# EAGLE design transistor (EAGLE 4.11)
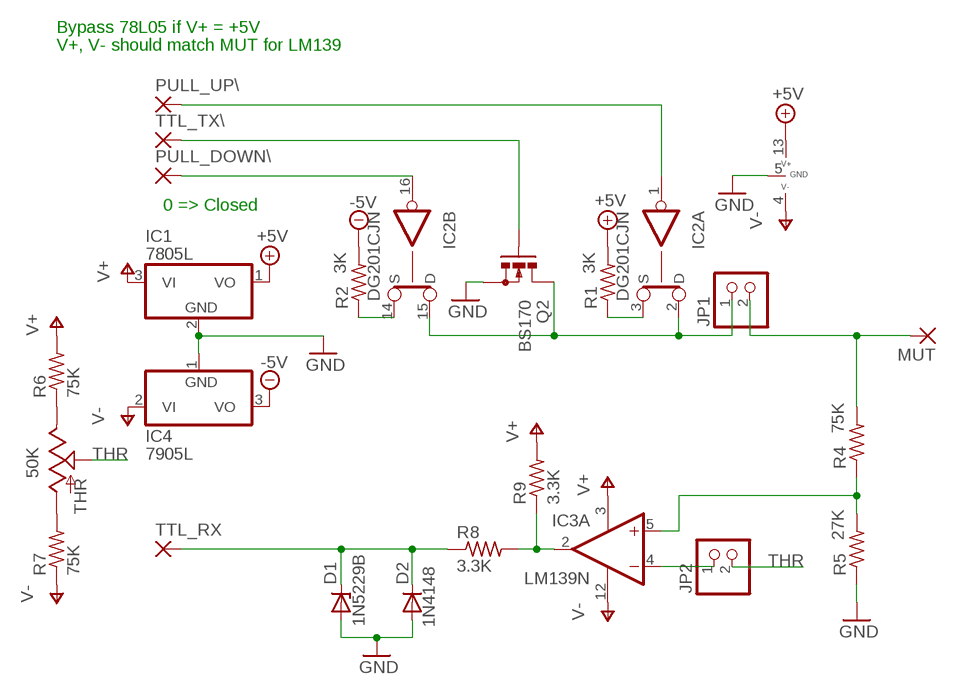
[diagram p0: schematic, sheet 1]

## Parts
D1  1N5229B  ZENER-DIODEDO35Z10  [DO35Z10]
D2  1N4148  [DO35-10]
IC1  7805L  [TO92]
IC2  DG201CJN  [DIL16]
IC3  LM139N  LM339N  [DIL14]
IC4  7905L  [TO92]
JP1  PINHD-1X2  [1X02]
JP2  PINHD-1X2  [1X02]
MUT  1,6/0,9  [1,6/0,9]
PULL_DOWN\  1,6/0,9  [1,6/0,9]
PULL_UP\  1,6/0,9  [1,6/0,9]
Q2  BS170  [SOT54E]
R1  3K  R-US_0207/10  [0207/10]
R2  3K  R-US_0207/10  [0207/10]
R4  75K  R-US_0207/10  [0207/10]
R5  27K  R-US_0207/10  [0207/10]
R6  75K  R-US_0207/10  [0207/10]
R7  75K  R-US_0207/10  [0207/10]
R8  3.3K  R-US_0207/10  [0207/10]
R9  3.3K  R-US_0207/10  [0207/10]
THR  50K  TRIM_US-S43P  [SP19L]
TTL_RX  1,6/0,9  [1,6/0,9]
TTL_TX\  1,6/0,9  [1,6/0,9]

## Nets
+5V: IC1.1(VO) IC2.13(P:V+) R1.2
-5V: IC4.3(VO) R2.2
GND: D1.A D2.A IC1.2(GND) IC2.5(P:GND) IC4.1(GND) Q2.S R5.1
N$1: IC2.3(A:S) R1.1
N$2: IC2.14(B:S) R2.1
N$3: Q2.G TTL_TX\.1(P)
N$4: IC2.16(B:IN) PULL_DOWN\.1(P)
N$5: IC2.2(A:D) IC2.15(B:D) JP1.1 Q2.D
N$6: JP1.2 MUT.1(P) R4.2
N$7: IC3.5(A:+IN) R4.1 R5.2
N$8: IC3.4(A:-IN) JP2.1
N$9: IC3.2(A:OUT) R8.2 R9.1
N$10: IC2.1(A:IN) PULL_UP\.1(P)
N$12: D1.C D2.C R8.1 TTL_RX.1(P)
N$13: R6.1 THR.E
N$14: R7.2 THR.A
THR: JP2.2 THR.S
V+: IC1.3(VI) IC3.3(P:V+) R6.2 R9.2
V-: IC2.4(P:V-) IC3.12(P:GND) IC4.2(VI) R7.1
Unconnected: IC2.6(D:S) IC2.7(D:D) IC2.8(D:IN) IC2.9(C:IN) IC2.10(C:D) IC2.11(C:S) IC3.1(B:OUT) IC3.6(B:-IN) IC3.7(B:+IN) IC3.8(C:-IN) IC3.9(C:+IN) IC3.10(D:-IN) IC3.11(D:+IN) IC3.13(D:OUT) IC3.14(C:OUT)

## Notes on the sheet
- Bypass 78L05 if V+ = +5V
- V+, V- should match MUT for LM139
- 0 => Closed

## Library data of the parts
D1 = diode:ZENER-DIODE: Z-Diode
D2 = diode:1N4148: DIODE
IC1 = linear:78*: Positive VOLTAGE REGULATOR
IC2 = linear:DG201CJ: CMOS SWITCH
IC3 = linear:LM339: Low Power Low Offset Voltage Quad Comparators with open collector; LM139/LM239/LM339/LM2901/LM3302
IC4 = linear:79*: Negative VOLTAGE REGULATOR
JP1 JP2 = pinhead:PINHD-1X2: PIN HEADER
MUT PULL_DOWN\ PULL_UP\ TTL_RX TTL_TX\ = wirepad:1,6/0,9: THROUGH-HOLE PAD
Q2 = transistor-small-signal:BS170: N-CHANNEL MOS FET
R1 R2 R4-R9 = rcl:R-US_: RESISTOR, American symbol
THR = pot:TRIM_US-: POTENTIOMETER

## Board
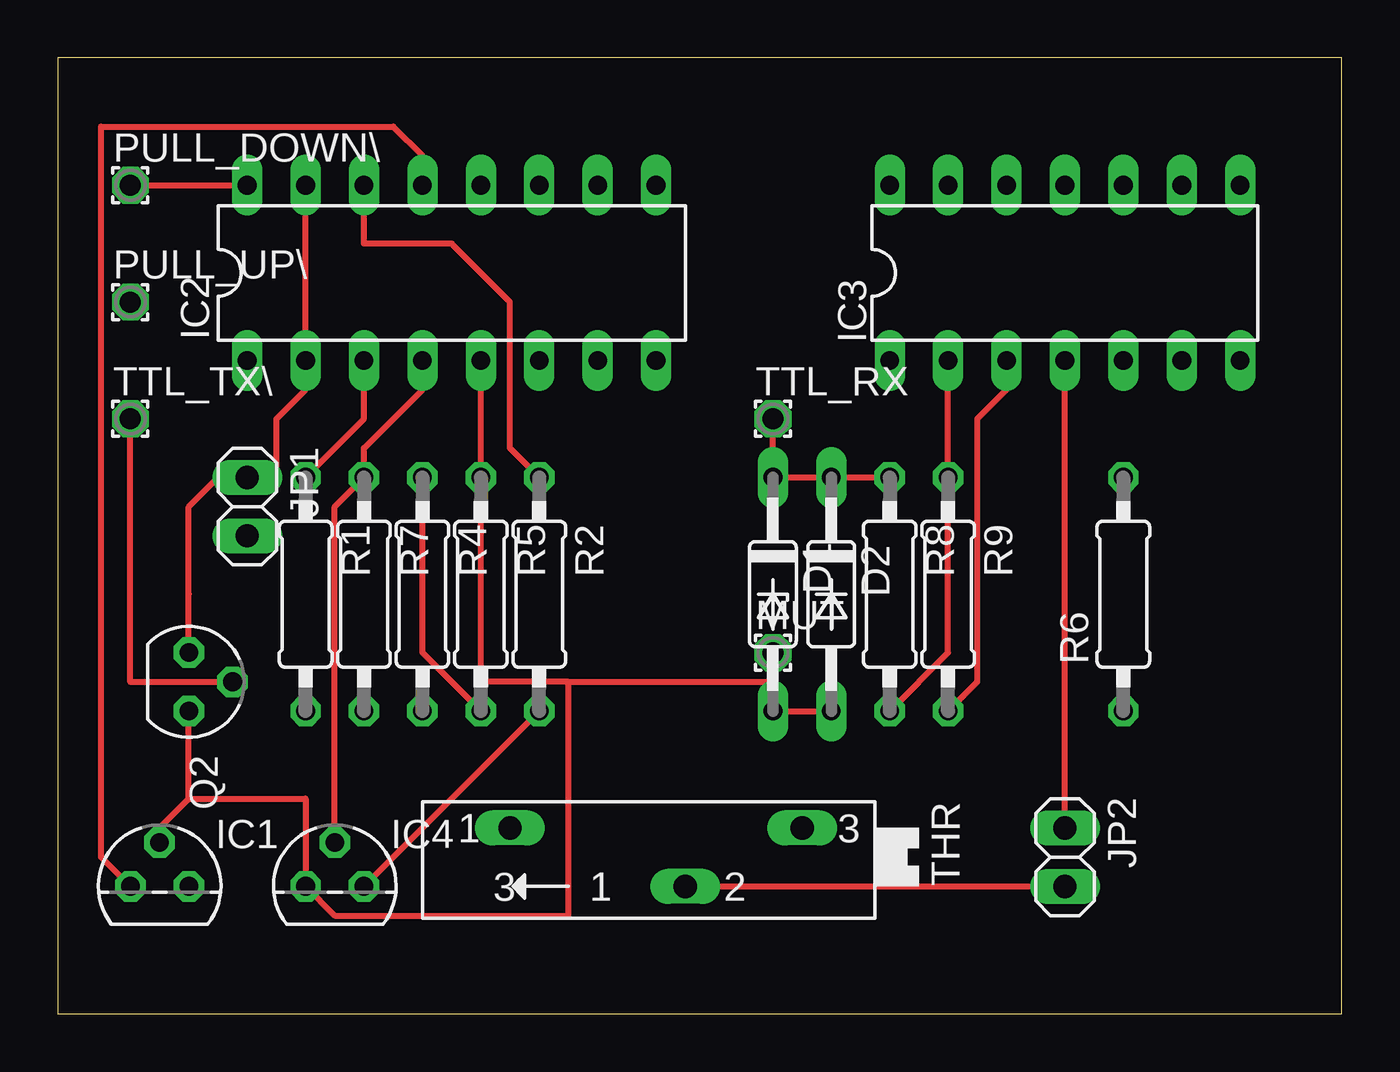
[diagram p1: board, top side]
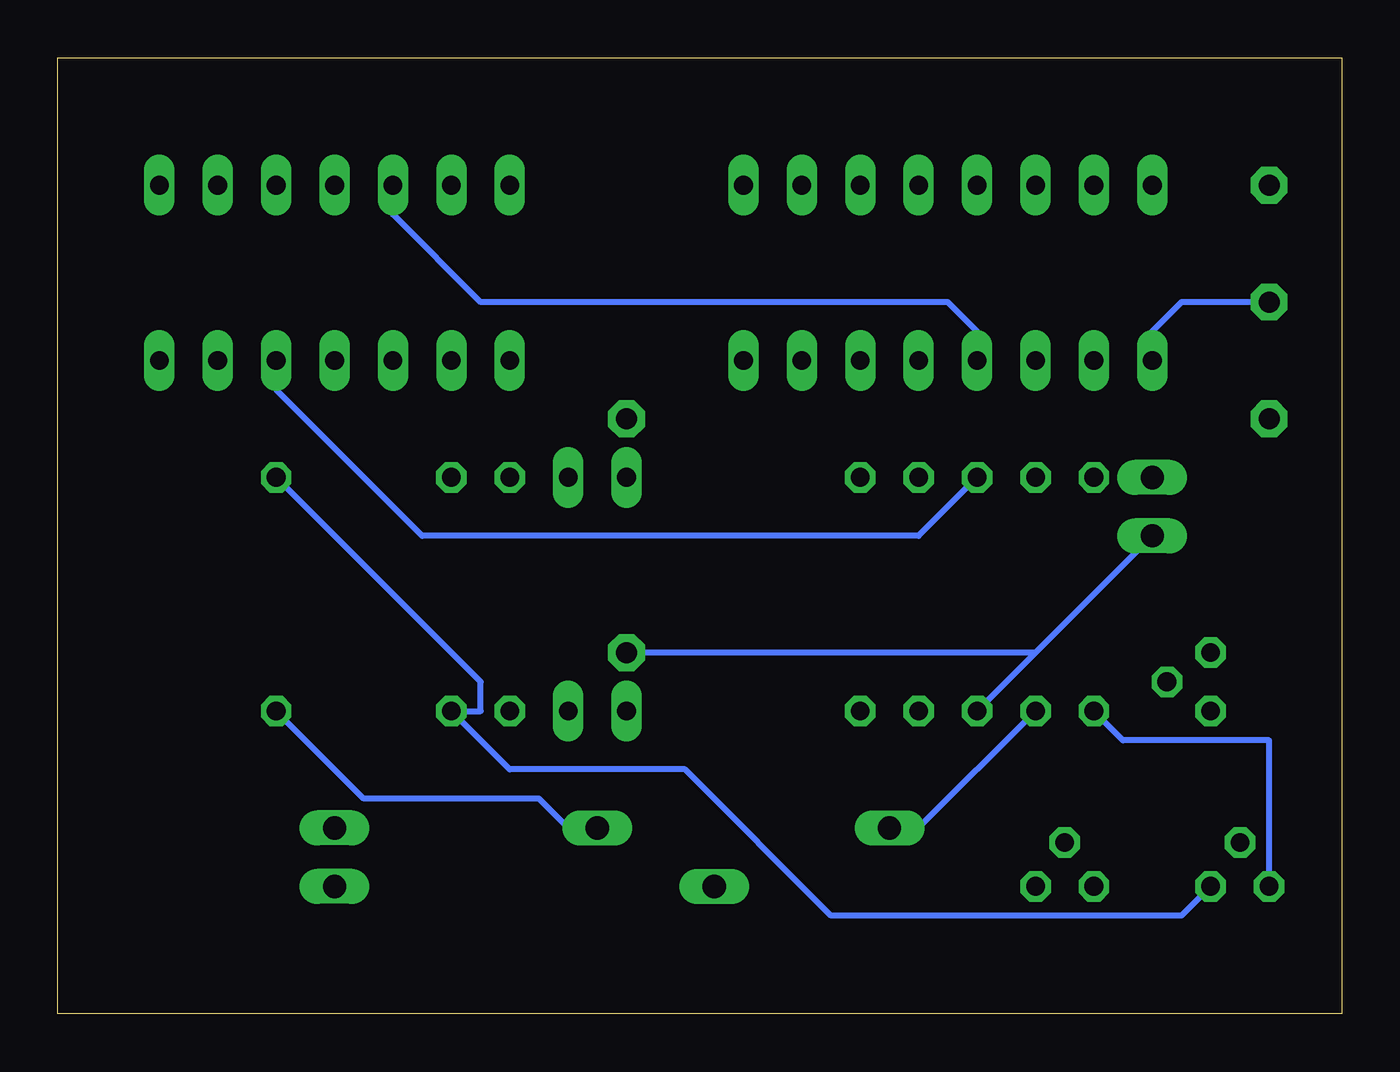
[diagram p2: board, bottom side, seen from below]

Size 55.86 x 41.58 mm. Coordinates in mm from the lower left corner, seen from the top.
Outline: 0,0 55.86,0 55.86,41.58 0,41.58 0,0
Copper layers (1*16): Top 0.035mm / dielectric 1.5mm / Bottom 0.035mm
Design rules "default": minimum track width 10mil, minimum drill 24mil, track to track 8mil, track to pad 8mil, pad to pad 8mil, via to via 8mil, smd to smd 8mil, copper to edge 40mil, drill to drill 8mil, minimum pad ring 10mil, minimum via ring 8mil, stop-mask expansion 4mil, vias tented up to drill 0mil, thermal gap 10mil

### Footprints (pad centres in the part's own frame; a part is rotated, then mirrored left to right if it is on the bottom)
DO35Z10 = drill 0.813 long: A 5.08,0; C -5.08,0
DO35-10 = drill 0.813 long: A 5.08,0; C -5.08,0
TO92 = drill 0.813 octagon: 1 -1.27,0; 2 0,1.905; 3 1.27,0
DIL16 = drill 0.813 long: 1 -8.89,-3.81; 2 -6.35,-3.81; 3 -3.81,-3.81; 4 -1.27,-3.81; 5 1.27,-3.81; 6 3.81,-3.81; 7 6.35,-3.81; 8 8.89,-3.81; 9 8.89,3.81; 10 6.35,3.81; 11 3.81,3.81; 12 1.27,3.81; 13 -1.27,3.81; 14 -3.81,3.81; 15 -6.35,3.81; 16 -8.89,3.81
DIL14 = drill 0.813 long: 1 -7.62,-3.81; 2 -5.08,-3.81; 3 -2.54,-3.81; 4 0,-3.81; 5 2.54,-3.81; 6 5.08,-3.81; 7 7.62,-3.81; 8 7.62,3.81; 9 5.08,3.81; 10 2.54,3.81; 11 0,3.81; 12 -2.54,3.81; 13 -5.08,3.81; 14 -7.62,3.81
1X02 = drill 1.016 long: 1 -1.27,0; 2 1.27,0
1,6/0,9 = drill 0.914 pad 1.6 octagon: 1 0,0
SOT54E = drill 0.813 octagon: D -1.27,0; G 0,1.905; S 1.27,0
0207/10 = drill 0.813 octagon: 1 -5.08,0; 2 5.08,0
SP19L = drill 1.016 long: A 5.715,-1.27; E -6.985,-1.27; S -1.905,1.27

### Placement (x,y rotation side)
D1  31.11,18.25 270 top
D2  33.65,18.25 270 top
IC1  4.44,5.55 0 top
IC2  17.14,32.22 0 top
IC3  43.81,32.22 0 top
IC4  12.06,5.55 0 top
JP1  8.25,22.06 270 top
JP2  43.81,6.82 270 top
MUT  31.11,15.71 0 top
PULL_DOWN\  3.17,36.03 0 top
PULL_UP\  3.17,30.95 0 top
Q2  5.71,14.44 270 top
R1  10.79,18.25 270 top
R2  20.95,18.25 270 top
R4  15.87,18.25 270 top
R5  18.41,18.25 270 top
R6  46.35,18.25 90 top
R7  13.33,18.25 270 top
R8  36.19,18.25 270 top
R9  38.73,18.25 270 top
THR  25.39,6.82 180 top
TTL_RX  31.11,25.87 0 top
TTL_TX\  3.17,25.87 0 top

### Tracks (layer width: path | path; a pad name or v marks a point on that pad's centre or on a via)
+5V
  Top 0.254: IC1.1 1.9,6.82 1.9,38.57 14.6,38.57 15.87,37.3 IC2.13
  Bottom 0.254: IC1.1 3.17,11.9 9.52,11.9 R1.2
-5V
  Top 0.254: IC4.3 R2.2
GND
  Top 0.254: D2.A D1.A 31.11,14.44 22.22,14.44 | IC2.5 18.41,27.14 R5.1 18.41,14.44 22.22,14.44 | 22.22,14.44 22.22,4.28 12.06,4.28 IC4.1 10.79,9.36 5.71,9.36 | 5.71,9.36 4.44,8.09 IC1.2 | 5.71,9.36 Q2.S
N$1
  Top 0.254: R1.1 13.33,25.87 13.33,27.14 IC2.3
N$2
  Top 0.254: R2.1 19.68,24.6 19.68,30.95 17.14,33.49 13.33,33.49 13.33,34.76 IC2.14
N$3
  Top 0.254: TTL_TX\.1 3.17,14.44 6.98,14.44 Q2.G
N$4
  Top 0.254: PULL_DOWN\.1 IC2.16
N$5
  Top 0.254: IC2.15 10.79,34.76 10.79,29.68 IC2.2 10.79,27.14 9.52,25.87 9.52,23.33 JP1.1 6.98,23.33 5.71,22.06 5.71,18.25 Q2.D
N$6
  Bottom 0.254: 13.33,15.71 JP1.2 | R4.2 13.33,15.71 | 13.33,15.71 MUT.1
N$7
  Top 0.254: R5.2 15.87,15.71 R4.1
  Bottom 0.254: R4.1 18.41,20.79 40,20.79 46.35,27.14 IC3.5
N$8
  Top 0.254: JP2.1 43.81,27.14 IC3.4
N$9
  Top 0.254: R8.2 38.73,15.71 R9.1 38.73,27.14 IC3.2
N$10
  Bottom 0.254: PULL_UP\.1 6.98,30.95 8.25,29.68 IC2.1
N$12
  Top 0.254: TTL_RX.1 31.11,24.6 D1.C D2.C R8.1
N$13
  Bottom 0.254: R6.1 42.54,9.36 34.92,9.36 33.65,8.09 THR.E
N$14
  Bottom 0.254: R7.2 18.41,8.09 THR.A
THR
  Top 0.254: THR.S 28.57,5.55 42.54,5.55 JP2.2
V+
  Top 0.254: R9.2 40,14.44 40,25.87 41.27,27.14 IC3.3
  Bottom 0.254: IC1.3 6.98,4.28 22.22,4.28 28.57,10.63 36.19,10.63 R9.2 37.46,13.17 37.46,14.44 R6.2
V-
  Top 0.254: IC4.2 12.06,8.09 12.06,22.06 R7.1 13.33,24.6 15.87,27.14 IC2.4
  Bottom 0.254: IC3.12 41.27,34.76 37.46,30.95 17.14,30.95 15.87,29.68 IC2.4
